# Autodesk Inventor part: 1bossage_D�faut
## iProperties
Created: 2011-01
Part Number: 1bossage_D�faut
Document SubType Name: Modeling
Designer: eric
Density: 1 g/cm^3
Mass: 2.87531 g
Surface Area: 30.2089 cm^2
Volume: 2.87531 cm^3
Author: eric
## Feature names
1. Base1
